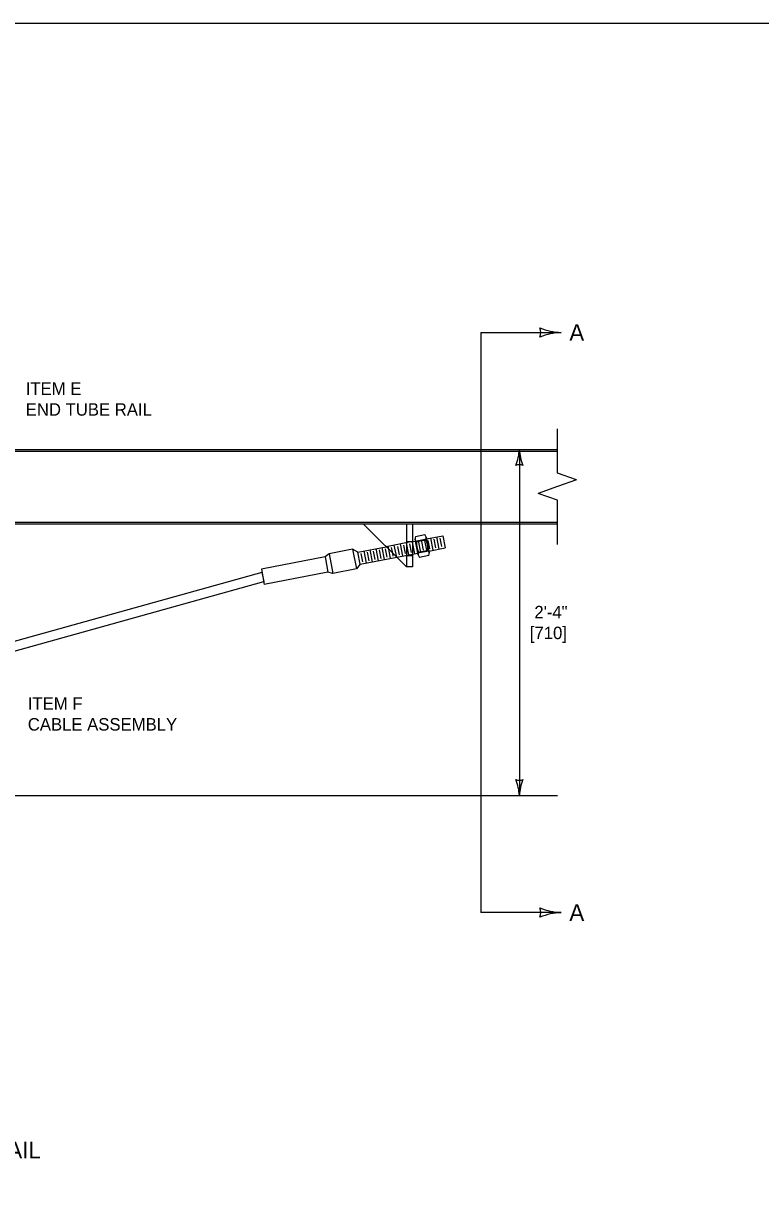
# Model space of a CAD drawing. Extents: x 49991.4 to 50021, y 49987.6 to 50011.4.
# Drawn here: x 50005.14 to 50008.69, y 49993.4 to 49999 of the extents above; entities that cross this region are included whole.
import ezdxf

# ---------------------------------------------------------------- set-up
doc = ezdxf.new("R2010")
doc.units = 0
for name, color, linetype in [('Level 1', 7, 'Continuous'), ('Level 2', 7, 'Continuous'), ('Level 3', 7, 'Continuous'), ('Level 4', 7, 'Continuous'), ('Level 6', 7, 'Continuous')]:
    doc.layers.add(name, color=color, linetype=linetype)

msp = doc.modelspace()

# ---------------------------------------------------------------- linework, layer by layer
at = {"layer": 'Level 1'}
for p, q in [((50002.6202, 49996.949), (50007.7121, 49996.949)), ((50003.7489, 49996.5925), (50007.7121, 49996.5925)), ((50006.9868, 49996.3846), (50006.7789, 49996.5925)), ((50006.9868, 49996.5925), (50006.9868, 49996.3846)), ((50007.0165, 49996.5925), (50007.0165, 49996.3846)), ((50007.0435, 49996.4426), (50007.0288, 49996.5184)), ((50007.0298, 49996.5317), (50007.0751, 49996.5404)), ((50007.0347, 49996.5064), (50007.08, 49996.5152)), ((50007.081, 49996.5285), (50007.0957, 49996.4527)), ((50007.0828, 49996.5194), (50007.1618, 49996.5347)), ((50007.1147, 49996.4651), (50007.1034, 49996.5234)), ((50007.1276, 49996.4767), (50007.1197, 49996.5175)), ((50007.1439, 49996.4708), (50007.1326, 49996.5291)), ((50007.1568, 49996.4823), (50007.1489, 49996.5232)), ((50007.1618, 49996.5347), (50007.1731, 49996.4764)), ((50006.7281, 49996.4696), (50006.6151, 49996.4477)), ((50006.7281, 49996.4696), (50006.7465, 49996.3748)), ((50006.7535, 49996.4556), (50006.7281, 49996.4696)), ((50006.7535, 49996.4556), (50006.8894, 49996.482)), ((50006.794, 49996.4029), (50006.7827, 49996.4613)), ((50006.8231, 49996.4086), (50006.8118, 49996.4669)), ((50006.836, 49996.4202), (50006.8281, 49996.461)), ((50006.8523, 49996.4143), (50006.841, 49996.4726)), ((50006.8652, 49996.4258), (50006.8573, 49996.4666)), ((50006.8815, 49996.4199), (50006.8701, 49996.4782)), ((50006.8943, 49996.4315), (50006.8864, 49996.4723)), ((50006.9106, 49996.4256), (50006.9021, 49996.4693)), ((50007.0165, 49996.5066), (50007.0305, 49996.5093)), ((50007.0273, 49996.4482), (50007.0165, 49996.5037)), ((50007.0445, 49996.4559), (50007.0898, 49996.4647)), ((50007.0985, 49996.471), (50007.0906, 49996.5119)), ((50007.0941, 49996.4611), (50007.1731, 49996.4764)), ((50006.5954, 49996.4325), (50006.2892, 49996.3732)), ((50006.6151, 49996.4477), (50006.5954, 49996.4325)), ((50006.5954, 49996.4325), (50006.6095, 49996.3596)), ((50006.6151, 49996.4477), (50006.6335, 49996.3529)), ((50006.7648, 49996.3973), (50006.7535, 49996.4556)), ((50006.7648, 49996.3973), (50006.9401, 49996.4313)), ((50006.7777, 49996.4089), (50006.7698, 49996.4497)), ((50006.8069, 49996.4145), (50006.7989, 49996.4553)), ((50006.9235, 49996.4371), (50006.9209, 49996.4505)), ((50007.0165, 49996.4461), (50007.0418, 49996.451)), ((50007.0947, 49996.4394), (50007.0494, 49996.4306)), ((50006.292, 49996.3586), (50003.4954, 49995.5783)), ((50006.2892, 49996.3732), (50006.3033, 49996.3003)), ((50006.292, 49996.3586), (50006.3005, 49996.3149)), ((50006.6095, 49996.3596), (50006.3033, 49996.3003)), ((50006.6335, 49996.3529), (50006.6095, 49996.3596)), ((50006.7465, 49996.3748), (50006.6335, 49996.3529)), ((50006.7648, 49996.3973), (50006.7465, 49996.3748)), ((50007.0165, 49996.3846), (50006.9868, 49996.3846)), ((50003.5023, 49995.5343), (50006.3005, 49996.3149)), ((50002.5165, 49995.2856), (50007.7121, 49995.2856))]:
    msp.add_line(p, q, dxfattribs=at)
msp.add_lwpolyline([(49999.3835, 49998.9992), (50016.7501, 49998.9992), (50016.7501, 49987.7988), (49999.3835, 49987.7988)], close=True, dxfattribs=at)
for centre, radius, start, end in [((50007.0533, 49996.5231), 0.025, 159.988, 221.9478), ((50007.0565, 49996.5237), 0.025, 339.988, 41.9478), ((50006.9955, 49996.4726), 0.0946, 355.1897, 26.7461), ((50007.129, 49996.4985), 0.0946, 175.1896, 206.7461), ((50007.0712, 49996.448), 0.025, 339.988, 41.9478), ((50007.068, 49996.4474), 0.025, 159.988, 221.9478)]:
    msp.add_arc(centre, radius, start, end, dxfattribs=at)
at = {"layer": 'Level 3'}
msp.add_line((50007.5295, 49996.949), (50007.5295, 49995.2856), dxfattribs=at)
for centre, radius, start, end in [((50007.3073, 49996.9581), 0.2223, 337.456, 357.6395), ((50007.7622, 49996.9605), 0.233, 182.8273, 202.0772), ((50007.5295, 49996.8208), 0.0548, 72.1388, 107.8612), ((50007.5295, 49995.4138), 0.0548, 252.1388, 287.8612), ((50007.2968, 49995.2741), 0.233, 2.8273, 22.0772), ((50007.7516, 49995.2764), 0.2223, 157.456, 177.6395)]:
    msp.add_arc(centre, radius, start, end, dxfattribs=at)
at = {"layer": 'Level 4'}
for p, q in [((50002.6202, 49996.9416), (50007.7121, 49996.9416)), ((50003.7489, 49996.6), (50007.7121, 49996.6)), ((50007.0305, 49996.5093), (50007.0828, 49996.5194)), ((50007.0856, 49996.4595), (50007.0743, 49996.5178)), ((50007.016, 49996.5065), (50006.8894, 49996.482)), ((50006.9021, 49996.4693), (50006.8993, 49996.4839)), ((50006.9209, 49996.4505), (50006.9156, 49996.478)), ((50006.9398, 49996.4312), (50006.9285, 49996.4895)), ((50006.9527, 49996.4428), (50006.9447, 49996.4836)), ((50006.9689, 49996.4369), (50006.9576, 49996.4952)), ((50006.9818, 49996.4484), (50006.9739, 49996.4893)), ((50006.9868, 49996.5071), (50007.0165, 49996.5071)), ((50006.9981, 49996.4425), (50006.9868, 49996.5008)), ((50007.011, 49996.4541), (50007.0031, 49996.4949)), ((50007.0941, 49996.4611), (50007.0418, 49996.451)), ((50007.0564, 49996.4538), (50007.0451, 49996.5121)), ((50007.0693, 49996.4654), (50007.0614, 49996.5062)), ((50006.9398, 49996.4312), (50007.0165, 49996.4461)), ((50006.9868, 49996.4403), (50007.0165, 49996.4403))]:
    msp.add_line(p, q, dxfattribs=at)
at = {"layer": 'Level 6'}
for p, q in [((50007.3436, 49997.5121), (50007.7299, 49997.5121)), ((50007.3436, 49997.5121), (50007.3436, 49996.989)), ((50007.7121, 49996.8355), (50007.7121, 49997.049)), ((50007.3436, 49996.989), (50007.3436, 49994.7225)), ((50007.8035, 49996.8031), (50007.7121, 49996.8355)), ((50007.8035, 49996.8031), (50007.7121, 49996.7707)), ((50007.7121, 49996.7707), (50007.6207, 49996.7383)), ((50007.7121, 49996.7059), (50007.6207, 49996.7383)), ((50007.7121, 49996.4925), (50007.7121, 49996.7059)), ((50007.7299, 49994.7225), (50007.3436, 49994.7225))]:
    msp.add_line(p, q, dxfattribs=at)
for centre, radius, start, end in [((50007.7422, 49997.8083), 0.2964, 247.456, 267.6395), ((50007.559, 49997.5121), 0.073, 342.1388, 17.8612), ((50007.7453, 49997.2018), 0.3107, 92.8273, 112.0772), ((50007.7422, 49995.0187), 0.2964, 247.456, 267.6395), ((50007.559, 49994.7225), 0.073, 342.1388, 17.8612), ((50007.7453, 49994.4122), 0.3107, 92.8273, 112.0772)]:
    msp.add_arc(centre, radius, start, end, dxfattribs=at)

# ---------------------------------------------------------------- texts
at = {"layer": 'Level 2'}
for s, height, p in [('A', 0.08, (50007.7699, 49997.4721)), ('ITEM E ', 0.06, (50005.1567, 49997.212)), ('END TUBE RAIL', 0.06, (50005.1567, 49997.112)), ('2\'-4"', 0.06, (50007.6016, 49996.1373)), ('[710]', 0.06, (50007.5799, 49996.0373)), ('ITEM F ', 0.06, (50005.1666, 49995.6976)), ('CABLE ASSEMBLY', 0.06, (50005.1666, 49995.5976)), ('A', 0.08, (50007.7699, 49994.6825)), ('BOX BEAM HEAD DETAIL', 0.08, (50003.9391, 49993.54))]:
    msp.add_text(s, height=height, dxfattribs=at).set_placement(p)

doc.saveas('drawing.dxf')
